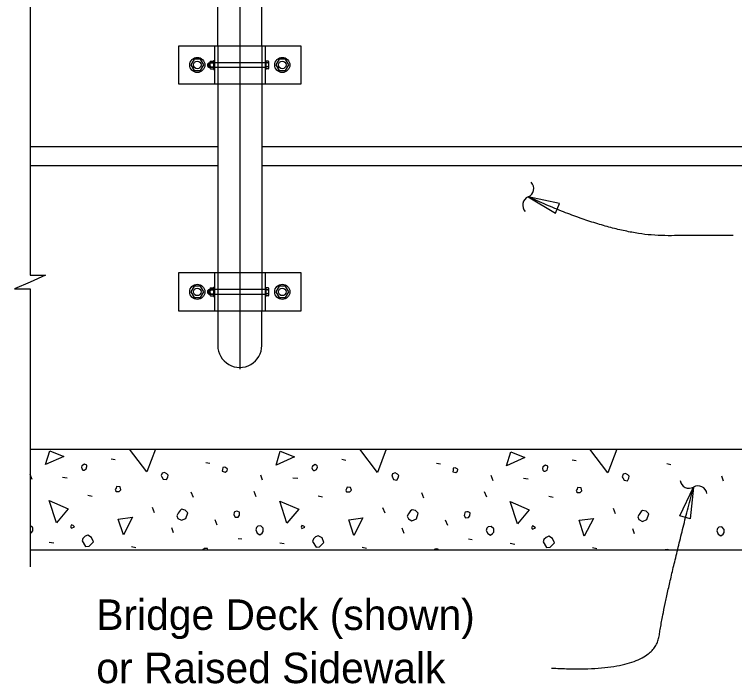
# Model space of a CAD drawing. Extents: x 0.5 to 39.7, y 0.9 to 25.6.
# Drawn here: x 0.716 to 5.477, y 12.586 to 17.01 of the extents above; entities that cross this region are included whole.
import ezdxf

# ---------------------------------------------------------------- set-up
doc = ezdxf.new("R2010")
doc.units = 0
for name, color, linetype in [('CL_Major', 7, 'Continuous'), ('Dimension', 7, 'Continuous'), ('Miscellaneous', 7, 'Continuous'), ('SteelMisc', 7, 'Continuous'), ('SteelMisc_h', 7, 'Continuous'), ('SupstrConc', 7, 'Continuous')]:
    doc.layers.add(name, color=color, linetype=linetype)

msp = doc.modelspace()

# ---------------------------------------------------------------- linework, layer by layer
at = {"layer": 'CL_Major'}
msp.add_line((2.2062, 25.5043), (2.2062, 14.6639), dxfattribs=at)
at = {"layer": 'Dimension'}
for points in [[(0.8194, 20.1983), (0.8194, 19.1806), (0.9227, 19.1806), (0.8194, 19.1356), (0.716, 19.0906), (0.8194, 19.0906), (0.8194, 16.8862)], [(0.8194, 17.1362), (0.8194, 15.2854), (0.9227, 15.2854), (0.8194, 15.2404), (0.716, 15.1954), (0.8194, 15.1954), (0.8194, 13.3576)]]:
    msp.add_lwpolyline(points, dxfattribs=at)
for points in [[(4.1133, 15.8046), (4.2942, 15.6956), (4.32, 15.7612)], [(5.2051, 13.8856), (5.1828, 13.6755), (5.1149, 13.6946)]]:
    msp.add_lwpolyline(points, close=True, dxfattribs=at)
for centre, start, end in [((4.09, 15.8588), 292.7091, 44.4364), ((4.136, 15.7489), 112.7091, 224.4364), ((5.1759, 13.9368), 188.4294, 300.1567), ((5.2358, 13.8337), 8.4294, 120.1567)]:
    msp.add_arc(centre, 0.0596, start, end, dxfattribs=at)
for points in [[(5.467, 15.5476), (5.3703, 15.5476), (4.6709, 15.5476), (4.1132, 15.8046)], [(4.2666, 12.6889), (4.9423, 12.6495), (5.0161, 13.1567), (5.2052, 13.8855)]]:
    msp.add_open_spline(points, degree=2, dxfattribs=at)
at = {"layer": 'Miscellaneous'}
for p, q in [((1.9986, 16.6691), (1.9986, 16.6812)), ((2.0043, 16.6691), (2.0043, 16.6812)), ((1.9986, 15.1691), (1.9986, 15.1812)), ((2.0043, 15.1691), (2.0043, 15.1812)), ((1.3567, 14.0725), (1.3832, 14.0672)), ((1.9825, 14.0477), (2.009, 14.0424)), ((2.8805, 14.0689), (2.907, 14.0636)), ((4.4043, 14.0654), (4.4308, 14.0601)), ((3.5063, 14.0442), (3.5328, 14.0389)), ((5.0301, 14.0407), (5.0566, 14.0354)), ((0.8334, 13.9346), (0.821, 13.9682)), ((2.3572, 13.9311), (2.3448, 13.9646)), ((3.881, 13.9275), (3.8687, 13.9611)), ((5.4048, 13.924), (5.3925, 13.9576)), ((1.0332, 13.9505), (1.065, 13.947)), ((2.557, 13.947), (2.5888, 13.9434)), ((4.0808, 13.9434), (4.1126, 13.9399)), ((2.3148, 13.8215), (2.3006, 13.8568)), ((1.2011, 13.8321), (1.2294, 13.825)), ((1.8994, 13.8162), (1.8852, 13.8515)), ((2.7249, 13.8285), (2.7532, 13.8215)), ((3.4232, 13.8126), (3.409, 13.848)), ((3.8386, 13.8179), (3.8245, 13.8533)), ((4.2487, 13.825), (4.277, 13.8179)), ((1.643, 13.7154), (1.6289, 13.7507)), ((3.1669, 13.7119), (3.1527, 13.7472)), ((4.6907, 13.7083), (4.6765, 13.7437)), ((2.0567, 13.6341), (2.0426, 13.6694)), ((3.5805, 13.6305), (3.5664, 13.6659)), ((1.7686, 13.5828), (1.7562, 13.6164)), ((3.2924, 13.5793), (3.28, 13.6129)), ((4.8162, 13.5757), (4.8038, 13.6093)), ((2.1946, 13.5457), (2.2193, 13.5421)), ((3.7184, 13.5421), (3.7431, 13.5386)), ((0.9465, 13.5209), (0.9766, 13.5156)), ((1.491, 13.4927), (1.5193, 13.4856)), ((2.4704, 13.5174), (2.5004, 13.5121)), ((3.0148, 13.4891), (3.0431, 13.482)), ((3.9942, 13.5139), (4.0242, 13.5086)), ((4.5386, 13.4856), (4.5669, 13.4785))]:
    msp.add_line(p, q, dxfattribs=at)
for points in [[(0.9218, 14.0336), (0.9501, 14.1255), (1.0438, 14.0884), (0.9218, 14.0336)], [(1.5918, 13.9859), (1.4776, 14.1361)], [(1.6479, 14.1361), (1.5918, 13.9859)], [(2.4456, 14.0301), (2.4739, 14.122), (2.5676, 14.0849), (2.4456, 14.0301)], [(3.1156, 13.9823), (2.9987, 14.1361)], [(3.1731, 14.1361), (3.1156, 13.9823)], [(3.9694, 14.0265), (3.9977, 14.1184), (4.0914, 14.0813), (3.9694, 14.0265)], [(4.6394, 13.9788), (4.5198, 14.1361)], [(4.6982, 14.1361), (4.6394, 13.9788)], [(1.1693, 13.9982), (1.1763, 13.9982), (1.1905, 14.0053), (1.1958, 14.0212), (1.194, 14.0301), (1.1799, 14.0371), (1.1622, 14.0265), (1.1587, 14.0159), (1.1622, 14.0053), (1.1693, 13.9982)], [(2.0903, 13.9894), (2.1097, 13.9841), (2.1221, 13.9929), (2.1239, 14.0053), (2.1203, 14.0088), (2.1062, 14.0159), (2.0938, 14.0141), (2.0921, 14.0018), (2.0903, 13.9894)], [(2.6931, 13.9947), (2.7002, 13.9947), (2.7143, 14.0018), (2.7196, 14.0177), (2.7178, 14.0265), (2.7037, 14.0336), (2.686, 14.023), (2.6825, 14.0124), (2.686, 14.0018), (2.6931, 13.9947)], [(3.6141, 13.9859), (3.6335, 13.9806), (3.6459, 13.9894), (3.6477, 14.0018), (3.6442, 14.0053), (3.63, 14.0124), (3.6176, 14.0106), (3.6159, 13.9982), (3.6141, 13.9859)], [(4.2169, 13.9912), (4.224, 13.9912), (4.2381, 13.9982), (4.2434, 14.0141), (4.2417, 14.023), (4.2275, 14.0301), (4.2098, 14.0194), (4.2063, 14.0088), (4.2098, 13.9982), (4.2169, 13.9912)], [(1.6908, 13.954), (1.6996, 13.9381), (1.7208, 13.9346), (1.7297, 13.9505), (1.7332, 13.9646), (1.7244, 13.9735), (1.7084, 13.9823), (1.6925, 13.977), (1.6872, 13.9611), (1.6908, 13.954)], [(3.2146, 13.9505), (3.2234, 13.9346), (3.2446, 13.9311), (3.2535, 13.947), (3.257, 13.9611), (3.2482, 13.9699), (3.2323, 13.9788), (3.2164, 13.9735), (3.211, 13.9576), (3.2146, 13.9505)], [(4.7384, 13.947), (4.7472, 13.9311), (4.7685, 13.9275), (4.7773, 13.9434), (4.7808, 13.9576), (4.772, 13.9664), (4.7561, 13.9753), (4.7402, 13.9699), (4.7349, 13.954), (4.7384, 13.947)], [(1.3885, 13.8568), (1.4097, 13.8568), (1.4203, 13.8674), (1.415, 13.8869), (1.392, 13.8886), (1.3885, 13.878), (1.3832, 13.8692), (1.3885, 13.8568), (1.3849, 13.8603)], [(2.9123, 13.8533), (2.9335, 13.8533), (2.9441, 13.8639), (2.9388, 13.8833), (2.9158, 13.8851), (2.9123, 13.8745), (2.907, 13.8657), (2.9123, 13.8533), (2.9088, 13.8568)], [(4.4361, 13.8497), (4.4573, 13.8497), (4.4679, 13.8603), (4.4626, 13.8798), (4.4396, 13.8816), (4.4361, 13.871), (4.4308, 13.8621), (4.4361, 13.8497), (4.4326, 13.8533)], [(0.9943, 13.65), (0.9465, 13.7967), (1.0721, 13.7419), (0.9943, 13.65)], [(2.5181, 13.6464), (2.4704, 13.7932), (2.5959, 13.7384), (2.5181, 13.6464)], [(4.0419, 13.6429), (3.9942, 13.7896), (4.1197, 13.7348), (4.0419, 13.6429)], [(1.7968, 13.6783), (1.8198, 13.6659), (1.8499, 13.6783), (1.8622, 13.7154), (1.8446, 13.7331), (1.8216, 13.7384), (1.811, 13.7313), (1.7986, 13.7119), (1.7898, 13.6959), (1.7968, 13.6783)], [(2.1663, 13.7012), (2.1751, 13.6853), (2.1946, 13.6871), (2.2034, 13.6995), (2.2052, 13.7189), (2.1928, 13.7242), (2.184, 13.726), (2.1734, 13.7225), (2.1698, 13.7189), (2.1663, 13.7012)], [(3.3207, 13.6747), (3.3436, 13.6624), (3.3737, 13.6747), (3.3861, 13.7119), (3.3684, 13.7295), (3.3454, 13.7348), (3.3348, 13.7278), (3.3224, 13.7083), (3.3136, 13.6924), (3.3207, 13.6747)], [(3.6901, 13.6977), (3.699, 13.6818), (3.7184, 13.6836), (3.7272, 13.6959), (3.729, 13.7154), (3.7166, 13.7207), (3.7078, 13.7225), (3.6972, 13.7189), (3.6936, 13.7154), (3.6901, 13.6977)], [(4.8445, 13.6712), (4.8674, 13.6588), (4.8975, 13.6712), (4.9099, 13.7083), (4.8922, 13.726), (4.8692, 13.7313), (4.8586, 13.7242), (4.8462, 13.7048), (4.8374, 13.6889), (4.8445, 13.6712)], [(1.4362, 13.5687), (1.4026, 13.673), (1.4963, 13.6853), (1.4362, 13.5687)], [(2.96, 13.5651), (2.9264, 13.6694), (3.0201, 13.6818), (2.96, 13.5651)], [(4.4838, 13.5616), (4.4503, 13.6659), (4.5439, 13.6783), (4.4838, 13.5616)], [(0.8193, 13.5766), (0.8299, 13.5846), (0.8369, 13.5952), (0.8369, 13.6164), (0.821, 13.6323), (0.8193, 13.6321)], [(1.0933, 13.6146), (1.1127, 13.6235), (1.1056, 13.6305), (1.0933, 13.6358), (1.088, 13.6235), (1.0933, 13.6146)], [(2.3113, 13.6023), (2.3219, 13.581), (2.3395, 13.5704), (2.3537, 13.581), (2.3608, 13.5916), (2.3608, 13.6129), (2.3448, 13.6288), (2.3254, 13.627), (2.3166, 13.6182), (2.3113, 13.6023)], [(2.6171, 13.6111), (2.6365, 13.6199), (2.6295, 13.627), (2.6171, 13.6323), (2.6118, 13.6199), (2.6171, 13.6111)], [(3.8351, 13.5987), (3.8457, 13.5775), (3.8634, 13.5669), (3.8775, 13.5775), (3.8846, 13.5881), (3.8846, 13.6093), (3.8687, 13.6252), (3.8492, 13.6235), (3.8404, 13.6146), (3.8351, 13.5987)], [(4.1409, 13.6076), (4.1603, 13.6164), (4.1533, 13.6235), (4.1409, 13.6288), (4.1356, 13.6164), (4.1409, 13.6076)], [(5.3589, 13.5952), (5.3695, 13.574), (5.3872, 13.5634), (5.4013, 13.574), (5.4084, 13.5846), (5.4084, 13.6058), (5.3925, 13.6217), (5.373, 13.6199), (5.3642, 13.6111), (5.3589, 13.5952)], [(1.164, 13.5298), (1.187, 13.4927), (1.2099, 13.4944), (1.2188, 13.5033), (1.2382, 13.5227), (1.2258, 13.5528), (1.2011, 13.5669), (1.1834, 13.5598), (1.1693, 13.5457), (1.164, 13.5298)], [(2.6878, 13.5262), (2.7108, 13.4891), (2.7338, 13.4909), (2.7426, 13.4997), (2.762, 13.5192), (2.7497, 13.5492), (2.7249, 13.5634), (2.7072, 13.5563), (2.6931, 13.5421), (2.6878, 13.5262)], [(4.2116, 13.5227), (4.2346, 13.4856), (4.2576, 13.4873), (4.2664, 13.4962), (4.2859, 13.5156), (4.2735, 13.5457), (4.2487, 13.5598), (4.2311, 13.5528), (4.2169, 13.5386), (4.2116, 13.5227)], [(1.9949, 13.4695), (1.9931, 13.4785), (1.9842, 13.4803), (1.9718, 13.4785), (1.9628, 13.4695)], [(3.518, 13.4695), (3.5169, 13.475), (3.508, 13.4767), (3.4957, 13.475), (3.4901, 13.4695)], [(5.0411, 13.4695), (5.0407, 13.4714), (5.0318, 13.4732), (5.0195, 13.4714), (5.0175, 13.4695)]]:
    msp.add_lwpolyline(points, dxfattribs=at)
at = {"layer": 'SteelMisc'}
for p, q in [((2.0603, 16.801), (2.0603, 17.4631)), ((2.352, 16.801), (2.352, 17.4631)), ((2.6121, 16.801), (1.8002, 16.801)), ((1.8002, 16.801), (1.8002, 16.551)), ((2.0395, 16.801), (2.0395, 16.551)), ((2.3728, 16.801), (2.3728, 16.551)), ((2.6121, 16.551), (2.6121, 16.801)), ((1.9958, 16.684), (2.0014, 16.6906)), ((1.9958, 16.6663), (1.9958, 16.684)), ((1.9958, 16.6663), (2.0014, 16.6607)), ((2.0014, 16.6906), (2.008, 16.6906)), ((2.0014, 16.6607), (2.0014, 16.6906)), ((2.008, 16.6939), (2.008, 16.6582)), ((2.0127, 16.689), (2.033, 16.689)), ((2.0129, 16.702), (2.033, 16.702)), ((2.033, 16.7063), (2.033, 16.6457)), ((2.033, 16.7063), (2.0395, 16.7063)), ((2.033, 16.702), (2.033, 16.65)), ((2.3791, 16.7063), (2.3731, 16.7063)), ((2.3791, 16.7063), (2.3791, 16.6457)), ((2.3938, 16.702), (2.3791, 16.702)), ((2.3939, 16.689), (2.3791, 16.689)), ((2.3989, 16.6566), (2.3989, 16.6955)), ((2.0014, 16.6607), (2.008, 16.6607)), ((2.0127, 16.6631), (2.033, 16.6631)), ((2.013, 16.65), (2.033, 16.65)), ((2.033, 16.6457), (2.0395, 16.6457)), ((2.3791, 16.6457), (2.3731, 16.6457)), ((2.3939, 16.663), (2.3791, 16.663)), ((2.3938, 16.65), (2.3791, 16.65)), ((1.8002, 16.551), (2.6121, 16.551)), ((2.0603, 16.551), (2.0603, 15.301)), ((2.352, 16.551), (2.352, 15.301)), ((2.6121, 15.301), (1.8002, 15.301)), ((1.8002, 15.301), (1.8002, 15.051)), ((2.0395, 15.301), (2.0395, 15.051)), ((2.3728, 15.301), (2.3728, 15.051)), ((2.6121, 15.051), (2.6121, 15.301)), ((1.9958, 15.184), (2.0014, 15.1906)), ((2.0014, 15.1906), (2.008, 15.1906)), ((2.0014, 15.1607), (2.0014, 15.1906)), ((2.008, 15.1939), (2.008, 15.1582)), ((2.0127, 15.189), (2.033, 15.189)), ((2.0129, 15.202), (2.033, 15.202)), ((2.033, 15.2063), (2.033, 15.1457)), ((2.033, 15.2063), (2.0395, 15.2063)), ((2.033, 15.202), (2.033, 15.15)), ((2.3791, 15.2063), (2.3731, 15.2063)), ((2.3791, 15.2063), (2.3791, 15.1457)), ((2.3938, 15.202), (2.3791, 15.202)), ((2.3939, 15.189), (2.3791, 15.189)), ((2.3989, 15.1566), (2.3989, 15.1955)), ((1.9958, 15.1663), (1.9958, 15.184)), ((1.9958, 15.1663), (2.0014, 15.1607)), ((2.0014, 15.1607), (2.008, 15.1607)), ((2.0127, 15.1631), (2.033, 15.1631)), ((2.013, 15.15), (2.033, 15.15)), ((2.033, 15.1457), (2.0395, 15.1457)), ((2.3791, 15.1457), (2.3731, 15.1457)), ((2.3939, 15.163), (2.3791, 15.163)), ((2.3938, 15.15), (2.3791, 15.15)), ((1.8002, 15.051), (2.6121, 15.051)), ((2.0602, 15.051), (2.0602, 14.8218)), ((2.3519, 14.8218), (2.3519, 15.051))]:
    msp.add_line(p, q, dxfattribs=at)
for points in [[(1.9468, 16.7135), (1.9035, 16.7135), (1.8818, 16.676), (1.9035, 16.6385), (1.9468, 16.6385), (1.9685, 16.676)], [(2.5088, 16.7135), (2.4655, 16.7135), (2.4438, 16.676), (2.4655, 16.6385), (2.5088, 16.6385), (2.5305, 16.676)], [(1.9468, 15.2135), (1.9035, 15.2135), (1.8818, 15.176), (1.9035, 15.1385), (1.9468, 15.1385), (1.9685, 15.176)], [(2.5088, 15.2135), (2.4655, 15.2135), (2.4438, 15.176), (2.4655, 15.1385), (2.5088, 15.1385), (2.5305, 15.176)]]:
    msp.add_lwpolyline(points, close=True, dxfattribs=at)
for centre, radius in [((1.9252, 16.676), 0.05), ((2.4871, 16.676), 0.05), ((1.9252, 16.676), 0.025), ((2.4871, 16.676), 0.025), ((1.9252, 15.176), 0.05), ((1.9252, 15.176), 0.025), ((2.4871, 15.176), 0.05), ((2.4871, 15.176), 0.025)]:
    msp.add_circle(centre, radius, dxfattribs=at)
for centre, radius, start, end in [((2.0145, 16.6955), 0.00674, 104.4891, 254.1889), ((2.0274, 16.676), 0.0196, 138.628, 221.372), ((2.3921, 16.6955), 0.00673, 285.7823, 75.5404), ((2.3792, 16.676), 0.0196, 318.628, 41.372), ((2.0145, 16.6565), 0.00673, 105.7823, 255.5404), ((2.3921, 16.6565), 0.00674, 284.4891, 74.1889), ((2.0145, 15.1955), 0.00674, 104.4891, 254.1889), ((2.0274, 15.176), 0.0196, 138.628, 221.372), ((2.3921, 15.1955), 0.00673, 285.7823, 75.5404), ((2.3792, 15.176), 0.0196, 318.628, 41.372), ((2.0145, 15.1565), 0.00673, 105.7823, 255.5404), ((2.3921, 15.1565), 0.00674, 284.4891, 74.1889)]:
    msp.add_arc(centre, radius, start, end, dxfattribs=at)
msp.add_ellipse((2.2062, 14.8218), major_axis=(0, 0.1458), ratio=0.999499, start_param=1.570796, end_param=4.712389, dxfattribs=at)
at = {"layer": 'SteelMisc_h'}
for p, q in [((2.0603, 16.801), (2.0603, 16.551)), ((2.352, 16.801), (2.352, 16.551)), ((2.3729, 16.6906), (2.008, 16.6906)), ((2.008, 16.6607), (2.3729, 16.6607)), ((2.0603, 15.301), (2.0603, 15.051)), ((2.352, 15.301), (2.352, 15.051)), ((2.3729, 15.1906), (2.008, 15.1906)), ((2.008, 15.1607), (2.3729, 15.1607))]:
    msp.add_line(p, q, dxfattribs=at)
at = {"layer": 'SupstrConc'}
for p, q in [((0.8193, 16.1361), (2.0603, 16.1361)), ((2.352, 16.1361), (12.0604, 16.1361)), ((0.8193, 16.0111), (2.0603, 16.0111)), ((2.352, 16.0111), (12.0604, 16.0111)), ((0.8193, 14.1361), (23.5931, 14.1361)), ((0.8193, 13.4695), (23.5931, 13.4695))]:
    msp.add_line(p, q, dxfattribs=at)

# ---------------------------------------------------------------- texts
at = {"layer": 'Dimension'}
for s, p in [('Bridge Deck (shown)', (1.2575, 12.9409)), ('or Raised Sidewalk', (1.2575, 12.5889))]:
    msp.add_text(s, height=0.2016, dxfattribs=at).set_placement(p)

doc.saveas('drawing.dxf')
